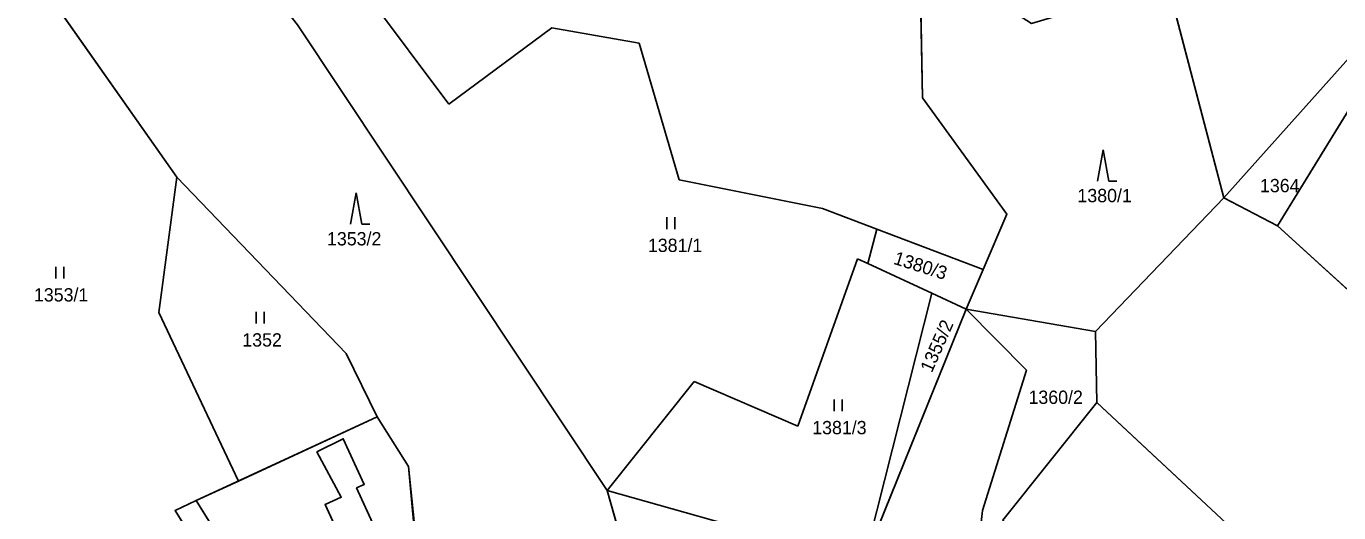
# Model space of a CAD drawing. Extents: x -760642 to -757221, y -1092371 to -1088855.
# Drawn here: x -758645.4 to -758477.6, y -1091492.4 to -1091430.2 of the extents above; entities that cross this region are included whole.
import ezdxf

# ---------------------------------------------------------------- set-up
doc = ezdxf.new("R2010")
doc.units = 0
for name, color, linetype in [('Vrstva 1', 7, 'Continuous'), ('Vrstva 18', 7, 'Continuous'), ('Vrstva 25', 7, 'Continuous'), ('Vrstva 26', 7, 'Continuous'), ('Vrstva 27', 7, 'Continuous'), ('Vrstva 30', 7, 'Continuous')]:
    doc.layers.add(name, color=color, linetype=linetype)

msp = doc.modelspace()

# ---------------------------------------------------------------- linework, layer by layer
at = {"layer": 'Vrstva 1'}
for p, q in [((-758658.56, -1091403.48), (-758626.15, -1091449.51)), ((-758591.38, -1091440.18), (-758609.16, -1091416.4)), ((-758460.11, -1091416.15), (-758492.28, -1091452.15)), ((-758531.18, -1091420.69), (-758530.81, -1091439.38)), ((-758499.5, -1091424.68), (-758492.28, -1091452.15)), ((-758610.74, -1091430.03), (-758571.13, -1091489.59)), ((-758578.22, -1091430.42), (-758591.38, -1091440.18)), ((-758567.04, -1091432.39), (-758578.22, -1091430.42)), ((-758561.93, -1091449.84), (-758567.04, -1091432.39)), ((-758472.46, -1091434.63), (-758485.44, -1091455.74)), ((-758530.81, -1091439.38), (-758520.04, -1091454.23)), ((-758626.15, -1091449.51), (-758628.46, -1091466.81)), ((-758626.15, -1091449.51), (-758604.53, -1091472.05)), ((-758561.93, -1091449.84), (-758543.62, -1091453.54)), ((-758508.7, -1091469.23), (-758492.28, -1091452.15)), ((-758492.28, -1091452.15), (-758485.44, -1091455.74)), ((-758543.62, -1091453.54), (-758536.67, -1091456.18)), ((-758520.04, -1091454.23), (-758523.08, -1091461.34)), ((-758536.67, -1091456.18), (-758537.82, -1091460.56)), ((-758536.67, -1091456.18), (-758523.08, -1091461.34)), ((-758485.44, -1091455.74), (-758463.98, -1091475.25)), ((-758539.12, -1091459.96), (-758546.77, -1091481.34)), ((-758537.82, -1091460.56), (-758539.12, -1091459.96)), ((-758529.64, -1091464.34), (-758537.82, -1091460.56)), ((-758523.08, -1091461.34), (-758525.24, -1091466.37)), ((-758538.34, -1091498.79), (-758529.64, -1091464.34)), ((-758525.24, -1091466.37), (-758529.64, -1091464.34)), ((-758628.46, -1091466.81), (-758618.29, -1091488.38)), ((-758538.34, -1091498.79), (-758525.24, -1091466.37)), ((-758508.7, -1091469.23), (-758525.24, -1091466.37)), ((-758525.24, -1091466.37), (-758517.53, -1091474.2)), ((-758508.55, -1091478.33), (-758508.7, -1091469.23)), ((-758600.53, -1091480.16), (-758604.53, -1091472.05)), ((-758517.53, -1091474.2), (-758523.16, -1091492.11)), ((-758560.01, -1091475.65), (-758571.13, -1091489.59)), ((-758546.77, -1091481.34), (-758560.01, -1091475.65)), ((-758508.55, -1091478.33), (-758520.53, -1091493.36)), ((-758503.35, -1091483.17), (-758508.55, -1091478.33)), ((-758600.53, -1091480.16), (-758618.29, -1091488.38)), ((-758600.53, -1091480.16), (-758596.54, -1091486.49)), ((-758604.88, -1091482.95), (-758608.24, -1091484.63)), ((-758602.19, -1091488.8), (-758604.88, -1091482.95)), ((-758492.01, -1091493.74), (-758503.35, -1091483.17)), ((-758608.24, -1091484.63), (-758605.14, -1091490.43)), ((-758596.54, -1091486.49), (-758595.42, -1091498.63)), ((-758618.29, -1091488.38), (-758623.67, -1091490.87)), ((-758603.18, -1091489.25), (-758602.19, -1091488.8)), ((-758598.27, -1091499.91), (-758603.18, -1091489.25)), ((-758571.13, -1091489.59), (-758538.34, -1091498.79)), ((-758566, -1091507.62), (-758571.13, -1091489.59)), ((-758623.67, -1091490.87), (-758626.39, -1091492.13)), ((-758623.67, -1091490.87), (-758613.71, -1091506.82)), ((-758605.14, -1091490.43), (-758607.21, -1091491.38)), ((-758607.21, -1091491.38), (-758602.43, -1091501.77)), ((-758626.39, -1091492.13), (-758616.47, -1091508.05)), ((-758523.16, -1091492.11), (-758524.32, -1091502.46))]:
    msp.add_line(p, q, dxfattribs=at)
at = {"layer": 'Vrstva 25'}
for p, q in [((-758507.722, -1091446.009), (-758508.455, -1091450.009)), ((-758507.722, -1091446.009), (-758506.989, -1091450.009)), ((-758506.989, -1091450.009), (-758505.989, -1091450.009)), ((-758603.232, -1091451.529), (-758603.965, -1091455.529)), ((-758603.232, -1091451.529), (-758602.499, -1091455.529)), ((-758563.527, -1091454.645), (-758563.527, -1091456.145)), ((-758562.505, -1091456.145), (-758562.505, -1091454.645)), ((-758602.499, -1091455.529), (-758601.499, -1091455.529)), ((-758641.627, -1091460.975), (-758641.627, -1091462.475)), ((-758640.605, -1091462.475), (-758640.605, -1091460.975)), ((-758615.997, -1091466.735), (-758615.997, -1091468.235)), ((-758614.975, -1091468.235), (-758614.975, -1091466.735)), ((-758542.127, -1091477.945), (-758542.127, -1091479.445)), ((-758541.105, -1091479.445), (-758541.105, -1091477.945))]:
    msp.add_line(p, q, dxfattribs=at)
at = {"layer": 'Vrstva 26'}
for points in [[(-758525.24, -1091466.37), (-758538.34, -1091498.79), (-758542.58, -1091509.28), (-758522.51, -1091528.22), (-758519.29, -1091515.5), (-758524.32, -1091502.46), (-758523.16, -1091492.11), (-758517.53, -1091474.2), (-758525.24, -1091466.37)], [(-758525.24, -1091466.37), (-758517.53, -1091474.2), (-758523.16, -1091492.11), (-758524.32, -1091502.46), (-758519.29, -1091515.5), (-758522.51, -1091528.22), (-758526.22, -1091532.15), (-758529.83, -1091534.46), (-758530.43, -1091535.02), (-758521.8, -1091563.51), (-758515.29, -1091559.76), (-758519.13, -1091559.11), (-758519.13, -1091534.43), (-758517.96, -1091529.21), (-758516.67, -1091525.31), (-758513.71, -1091515.45), (-758510.7, -1091505.43), (-758520.53, -1091493.36), (-758508.55, -1091478.33), (-758508.7, -1091469.23), (-758525.24, -1091466.37)], [(-758508.55, -1091478.33), (-758520.53, -1091493.36), (-758510.7, -1091505.43), (-758513.71, -1091515.45), (-758505.76, -1091517.86), (-758505.15, -1091516.8), (-758492.01, -1091493.74), (-758503.35, -1091483.17), (-758508.55, -1091478.33)], [(-758602.43, -1091501.77), (-758607.21, -1091491.38), (-758605.14, -1091490.43), (-758608.24, -1091484.63), (-758604.88, -1091482.95), (-758602.19, -1091488.8), (-758603.18, -1091489.25), (-758598.27, -1091499.91), (-758595.42, -1091498.63), (-758596.54, -1091486.49), (-758600.53, -1091480.16), (-758618.29, -1091488.38), (-758623.67, -1091490.87), (-758613.71, -1091506.82), (-758602.43, -1091501.77)], [(-758602.43, -1091501.77), (-758598.27, -1091499.91), (-758603.18, -1091489.25), (-758602.19, -1091488.8), (-758604.88, -1091482.95), (-758608.24, -1091484.63), (-758605.14, -1091490.43), (-758607.21, -1091491.38), (-758602.43, -1091501.77)], [(-758599.47, -1091526.49), (-758613.71, -1091506.82), (-758623.67, -1091490.87), (-758626.39, -1091492.13), (-758616.47, -1091508.05), (-758607.38, -1091520.63), (-758608.51, -1091523.87), (-758626.07, -1091528.79), (-758620.41, -1091533.51), (-758601.15, -1091527.44), (-758576.51, -1091518.65), (-758575.77, -1091517.87), (-758579.77, -1091515.84), (-758599.47, -1091526.49)]]:
    msp.add_lwpolyline(points, dxfattribs=at)
at = {"layer": 'Vrstva 27'}
for points in [[(-758492.01, -1091493.74), (-758508.55, -1091478.33), (-758508.7, -1091469.23), (-758525.24, -1091466.37), (-758538.34, -1091498.79)], [(-758594.278, -1091508.477), (-758596.54, -1091486.49), (-758600.53, -1091480.16), (-758623.67, -1091490.87), (-758626.39, -1091492.13), (-758616.47, -1091508.05)]]:
    msp.add_lwpolyline(points, dxfattribs=at)
at = {"layer": 'Vrstva 30'}
for points in [[(-758379, -1091364.77), (-758385.3, -1091361.15), (-758386.99, -1091358), (-758413.87, -1091370.38), (-758411.89, -1091375.25), (-758421.02, -1091389.6), (-758427.62, -1091418.91), (-758439.94, -1091418.19), (-758454.79, -1091429.96), (-758460.41, -1091424.53), (-758472.46, -1091434.63), (-758485.44, -1091455.74), (-758463.98, -1091475.25)], [(-758594.922, -1091502.221), (-758594.04, -1091508.58), (-758579.77, -1091515.84), (-758575.77, -1091517.87), (-758566, -1091507.62), (-758571.13, -1091489.59), (-758610.74, -1091430.03), (-758635.42, -1091398.76), (-758658.56, -1091403.48), (-758626.15, -1091449.51), (-758604.53, -1091472.05), (-758600.53, -1091480.16), (-758596.54, -1091486.49), (-758594.922, -1091502.221)], [(-758508.7, -1091469.23), (-758492.28, -1091452.15), (-758499.5, -1091424.68), (-758516.88, -1091429.87), (-758531.18, -1091420.69), (-758530.81, -1091439.38), (-758520.04, -1091454.23), (-758523.08, -1091461.34), (-758525.24, -1091466.37), (-758508.7, -1091469.23)], [(-758508.7, -1091469.23), (-758508.55, -1091478.33), (-758503.35, -1091483.17), (-758492.01, -1091493.74), (-758483.01, -1091502.12), (-758467.28, -1091516.76), (-758461.25, -1091521.35), (-758430.66, -1091538.42), (-758418.59, -1091530.76), (-758417.98, -1091522.55), (-758413.1, -1091521.32), (-758463.98, -1091475.25), (-758485.44, -1091455.74), (-758492.28, -1091452.15), (-758508.7, -1091469.23)], [(-758485.44, -1091455.74), (-758492.28, -1091452.15), (-758508.7, -1091469.23), (-758508.55, -1091478.33), (-758503.35, -1091483.17), (-758492.01, -1091493.74), (-758483.01, -1091502.12), (-758467.28, -1091516.76), (-758461.25, -1091521.35), (-758430.66, -1091538.42), (-758418.59, -1091530.76), (-758417.98, -1091522.55), (-758413.1, -1091521.32), (-758463.98, -1091475.25), (-758485.44, -1091455.74)]]:
    msp.add_lwpolyline(points, dxfattribs=at)

# ---------------------------------------------------------------- texts
at = {"layer": 'Vrstva 18'}
for s, p in [('1364', (-758487.67, -1091451.44)), ('1380/1', (-758511.01, -1091452.72)), ('1353/2', (-758606.96, -1091458.24)), ('1381/1', (-758565.93, -1091459.08)), ('1353/1', (-758644.43, -1091465.41)), ('1352', (-758617.79, -1091471.17)), ('1360/2', (-758517.27, -1091478.5)), ('1381/3', (-758544.92, -1091482.38))]:
    msp.add_text(s, height=1.7, dxfattribs=at).set_placement(p)
for s, rotation, p in [('1380/3', 342.57357, (-758534.64, -1091460.58)), ('1355/2', 66.05955, (-758529.63, -1091474.61))]:
    msp.add_text(s, height=1.7, rotation=rotation, dxfattribs=at).set_placement(p)

doc.saveas('drawing.dxf')
